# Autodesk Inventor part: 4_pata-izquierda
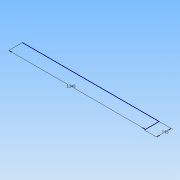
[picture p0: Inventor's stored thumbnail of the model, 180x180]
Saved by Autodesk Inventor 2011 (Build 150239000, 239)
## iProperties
Created: 2020-12
Part Number: 4_pata-izquierda
Document SubType Name: Modeling
Designer: PC
Density: 1 g/cm^3
Author: PC
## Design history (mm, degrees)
sketch "Sketch1"
  geometry: L1 (0, 0)-(1340, 0); L2 (1340, 0)-(1340, -145)
  constraints: 4 end point, 1 horizontal, 1 perpendicular
  dimensions: "d0" = 1340 dimension on L1.start L1.end L1 L2.end L2; "d0" = 1340 distance of L1.start L1.end; "d2" = 145 distance of L1.end L2.end
